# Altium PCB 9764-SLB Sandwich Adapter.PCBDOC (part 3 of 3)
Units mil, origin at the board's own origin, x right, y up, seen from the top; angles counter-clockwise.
Board outline 5593.84 x 1511.98 mil, 8 copper layers (Top Layer, MidLayer1, MidLayer2, MidLayer3, MidLayer4, MIdLayer5, MidLayer6, Bottom Layer); 137 components, 228 nets, 1508 pads, 0 vias.
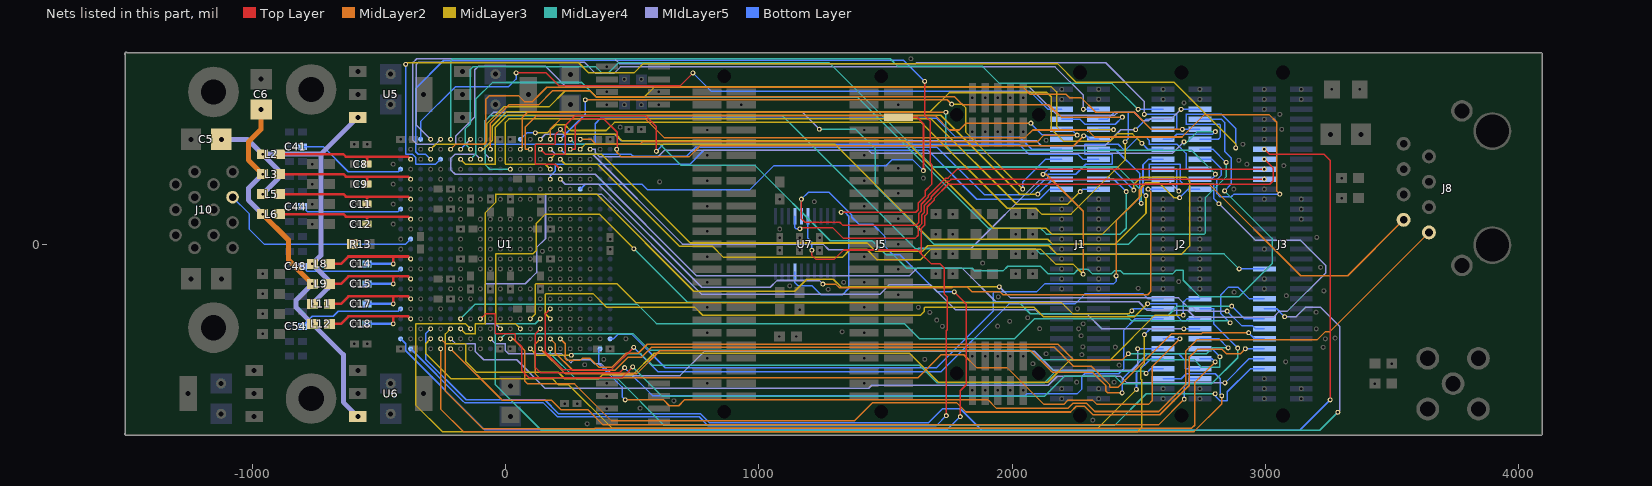
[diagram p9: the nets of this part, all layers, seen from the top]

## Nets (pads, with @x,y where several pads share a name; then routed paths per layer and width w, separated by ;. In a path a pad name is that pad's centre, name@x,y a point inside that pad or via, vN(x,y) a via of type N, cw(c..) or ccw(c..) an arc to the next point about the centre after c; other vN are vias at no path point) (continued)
SYNC3_0: J1.43 pad.0@2268.65,207 U1.T4 | length 2860.4
  MidLayer3 w6: U1.T4@177.17,295.28 157.44,315 1.15,315 0.15,316 0.15,480 13.99,493.84 1681,493.84 2017.84,157 2218.65,157 pad.0@2268.65,207
  Bottom Layer w6: pad.0@2268.65,207 2278.19,216.54 J1.43@2340.98,216.54
SYNC3_1: J1.44 U1.T5 | length 2184.1
  Bottom Layer w6: U1.T5@177.17,255.91 177.17,268.63 196.15,287.61 196.15,313 198.15,315 728.15,315 783.15,370 1667.31,370 1860.31,177 2108.2,177 2147.73,216.54 J1.44@2195.32,216.54
SYNC3_2: J1.45 pad.0@2450.15,207 U1.H3 | length 3371.7
  MidLayer4 w6: U1.H3@-137.8,334.65 -117.85,354.59 -117.85,571 -51.35,637.5 301.34,637.5 359.84,579 1389.15,579 1905.15,63 2111.15,63 2135.15,39 2426.65,39 2450.15,62.5 pad.0@2450.15,207
  Bottom Layer w6: J1.45@2340.98,255.91 2401.24,255.91 pad.0@2450.15,207
SYNC3_3: J1.46 pad.0@2101.15,197 U1.G3 | length 2700.4
  MidLayer3 w6: U1.G3@-177.17,334.65 -156.52,314 -40.85,314 -39.85,315 -39.85,460.03 8.12,508 1718.15,508 2030.15,196 2100.15,196 pad.0@2101.15,197
  Bottom Layer w6: pad.0@2101.15,197 2160.06,255.91 J1.46@2195.32,255.91
SYNC3_4: J1.47 pad.0@2480.15,213 U1.T3 | length 3417.6
  MidLayer3 w6: U1.T3@177.17,334.65 197.52,355 378.15,355 729.15,4 1428.15,4 1461.15,-29 1644.69,-29 1666.69,-7 2144.15,-7 2177.15,-40 2668.15,-40 2700.15,-8 2700.15,250 2686.15,264 2509.15,264 2480.15,235 pad.0@2480.15,213
  Bottom Layer w6: J1.47@2340.98,295.28 2397.87,295.28 pad.0@2480.15,213
SYNC3_5: J1.48 pad.0@2121.65,275 pad.0@2280.15,-119 U1.U3 | length 2861.9
  MidLayer2 w6: pad.0@2121.65,275 2134.15,275 2280.15,129 pad.0@2280.15,-119
  MidLayer3 w6: U1.U3@216.54,334.65 236.18,315 363.15,315 686.15,-8 816.15,-8 861.15,-53 1329.15,-53 1361.15,-21 1425.65,-21 1466.65,-62 1638.15,-62 1680.15,-20 2112.15,-20 2171.15,-79 2240.15,-79 pad.0@2280.15,-119
  Bottom Layer w6: pad.0@2121.65,275 2141.93,295.28 J1.48@2195.32,295.28
SYNC3_6: J1.49 pad.0@596.15,366 U1.R2 | length 2490.5
  Top Layer w6: U1.R2@137.8,374.02 157.81,354 234.15,354 236.15,356 236.15,467.5 274.65,506 552.65,506 596.15,462.5 pad.0@596.15,366
  Bottom Layer w6: pad.0@596.15,366 624.15,394 2027.15,394 2066.82,354.33 2259.51,354.33 2279.2,334.65 J1.49@2340.98,334.65
SYNC3_7: J1.50 pad.0@315.15,569 pad.0@1761.15,552 pad.0@2041.5,217 U1.U1 | length 2343.7
  MidLayer2 w6: pad.0@315.15,569 1744.15,569 pad.0@1761.15,552
  MidLayer3 w6: pad.0@1761.15,552 1802.65,552 1816.15,538.5 1816.15,442.35 pad.0@2041.5,217
  Bottom Layer w6: U1.U1@216.54,413.39 315.15,512 pad.0@315.15,569 ; pad.0@2041.5,217 2041.5,244.75 2131.4,334.65 J1.50@2195.32,334.65
SYNC3_8: J1.51 pad.0@2509.15,160.32 U1.H2 | length 3593.1
  MidLayer4 w6: U1.H2@-137.8,374.02 -157.85,394.07 -157.85,456 -138.85,475 -138.85,688.5 -126.85,700.5 355.65,700.5 381.15,675 406.15,675 447.15,716 1277.15,716 1689.15,304 2416.15,304 2509.15,211 pad.0@2509.15,160.32
  Bottom Layer w6: J1.51@2340.98,374.02 2407.04,374.02 2504.15,276.91 2504.15,165.32 pad.0@2509.15,160.32
SYNC4_0: J1.52 U1.G2 | length 2520.4
  Bottom Layer w6: U1.G2@-177.17,374.02 -158.18,393 352.15,393 354.15,395 354.15,475 375.15,496 1702.15,496 1776.15,422 2029.15,422 2077.13,374.02 J1.52@2195.32,374.02
SYNC4_1: J1.53 pad.0@439.15,374 pad.0@2282.15,427 U1.V2 | length 2339
  Top Layer w6: U1.V2@255.91,374.02 274.15,374.02 276.15,376.02 276.15,468 301.99,493.84 388.31,493.84 441.15,441 441.15,376 pad.0@439.15,374
  MidLayer2 w6: pad.0@439.15,374 439.15,362 456.15,345 726.15,345 769.15,388 2243.15,388 pad.0@2282.15,427
  Bottom Layer w6: pad.0@2282.15,427 2292.54,427 2306.15,413.39 J1.53@2340.98,413.39
SYNC4_2: J1.54 pad.0@2074.15,477 U1.P2 | length 2303.1
  MidLayer2 w6: U1.P2@98.43,374.02 80.15,374.02 79.15,375.02 79.15,462.5 122.49,505.84 1697.31,505.84 1753.15,450 1791.15,450 1818.15,477 pad.0@2074.15,477
  Bottom Layer w6: pad.0@2074.15,477 2074.15,475 2117.15,432 2174.54,432 2193.15,413.39 J1.54@2195.32,413.39
SYNC4_3: J1.55 pad.0@2399.89,451.5 U1.D2 | length 3066.7
  MidLayer3 w6: U1.D2@-295.28,374.02 -275.29,394 -85.85,394 -74.35,405.5 -74.35,473.5 -6.85,541 172.15,541 235.99,604.84 333.99,604.84 358.84,580 548.15,580 588.15,620 2155.15,620 2175.15,600 2175.15,463.5 2187.15,451.5 pad.0@2399.89,451.5
  Bottom Layer w6: J1.55@2340.98,452.76 2398.64,452.76 pad.0@2399.89,451.5
SYNC4_4: J1.56 pad.0@2256.15,430 U1.W1 | length 2054.9
  MidLayer2 w6: U1.W1@295.28,413.39 338.15,413.39 358.54,393 530.15,393 541.15,404 2100.15,404 2126.15,430 pad.0@2256.15,430
  Bottom Layer w6: J1.56@2195.32,452.76 2233.39,452.76 pad.0@2256.15,430
SYNC4_5: J1.57 pad.0@118.15,439 pad.0@2445.65,403.5 U1.N1 | length 2992.1
  MidLayer3 w6: pad.0@118.15,439 166.46,439 198.46,471 233.99,471 256.96,448.03 398.18,448.03 430.15,480 1641.15,480 1980.15,141 2093.15,141 2116.15,118 2232.15,118 2445.65,331.5 pad.0@2445.65,403.5
  Bottom Layer w6: U1.N1@59.06,413.39 84.67,439 pad.0@118.15,439 ; J1.57@2340.98,492.13 2376.15,492.13 2404.02,520 2454.99,520 2458.15,516.84 2458.15,416 pad.0@2445.65,403.5
SYNC4_6: J1.58 pad.0@2435.15,501 U1.K2 | length 2952
  MidLayer2 w6: U1.K2@-59.06,374.02 -59.06,476.79 13.15,549 130.15,549 185.15,604 334.84,604 357.84,581 1772.65,581 1803.65,550 2144.65,550 2193.65,501 pad.0@2435.15,501
  Bottom Layer w6: J1.58@2195.32,492.13 2268.15,492.13 2287.65,472.62 2406.77,472.62 pad.0@2435.15,501
SYNC4_7: J1.59 pad.0@2281.15,531.5 U1.D1 | length 3146.2
  MIdLayer5 w6: U1.D1@-295.28,413.39 -351.85,469.96 -351.85,708 -341.85,718 311.15,718 356.01,673.14 428.29,673.14 454.15,699 2169.15,699 2281.15,587 pad.0@2281.15,531.5
  Bottom Layer w6: pad.0@2281.15,531.5 J1.59@2340.98,531.5
SYNC4_8: J1.60 pad.0@42.15,675 pad.0@740.15,675 U1.C1 | length 2795
  Top Layer w6: pad.0@42.15,675 161.15,675 212.15,624 689.15,624 pad.0@740.15,675
  Bottom Layer w6: U1.C1@-334.65,413.39 -334.65,483.2 -197.85,620 11.15,620 42.15,651 pad.0@42.15,675 ; pad.0@740.15,675 813.15,602 2070.65,602 2141.15,531.5 J1.60@2195.32,531.5
SYNC5_0: J2.59 pad.0@2666.49,531.5 U1.H1 | length 3378.1
  MIdLayer5 w6: U1.H1@-137.8,413.39 -158.18,393 -194.85,393 -196.85,395 -196.85,425 -120.85,501 -120.85,687.5 -107.35,701 159.15,701 240.15,620 2067.15,620 2179.81,507.34 2403.81,507.34 2416.46,520 2481.66,520 2515.66,486 2537.3,486 2545.4,494.1 2629.1,494.1 pad.0@2666.49,531.5
  Bottom Layer w6: pad.0@2666.49,531.5 J2.59@2740.98,531.5
SYNC5_1: J2.60 pad.0@2496.91,531.5 U1.F1 | length 3206.8
  MidLayer4 w6: U1.F1@-216.54,413.39 -216.54,722 -207.54,731 1519.15,731 1549.15,701 1883.15,701 1950.15,634 2394.4,634 pad.0@2496.91,531.5
  Bottom Layer w6: pad.0@2496.91,531.5 J2.60@2595.32,531.5
SYNC5_2: J2.57 pad.0@2838.15,209.5 U1.V1 | length 3915.7
  MidLayer4 w6: U1.V1@255.91,413.39 276.29,393 611.15,393 694.15,310 985.15,310 1282.15,13 1447.31,13 1503.31,-43 1531.15,-43 1584.15,-96 1842.62,-96 1852.62,-106 1964.2,-106 1982.2,-88 2112.29,-88 2142.29,-118 2243.18,-118 2261.18,-100 2298.84,-100 2316.84,-118 2391.3,-118 2403.3,-106 2428.55,-106 2440.55,-118 2632.37,-118 2647.41,-102.96 2674.23,-102.96 2675.28,-104 2675.28,-142.63 2741.65,-209 2894.34,-209 3025.65,-77.69 3025.65,22 pad.0@2838.15,209.5
  Bottom Layer w6: J2.57@2740.98,492.13 2825.65,492.13 2838.15,479.63 2838.15,366.51 2864.15,340.51 2864.15,235.5 pad.0@2838.15,209.5
SYNC5_3: J2.58 pad.0@2487.15,451 U1.R1 | length 2527.4
  MIdLayer5 w6: U1.R1@137.8,413.39 157.41,433 430.15,433 456.15,407 2096.15,407 2115.15,388 2365.9,388 2428.9,451 pad.0@2487.15,451
  Bottom Layer w6: pad.0@2487.15,451 2528.28,492.13 J2.58@2595.32,492.13
SYNC5_4: J2.55 pad.0@2672.15,452.5 U1.F2 | length 3249.9
  MidLayer2 w6: U1.F2@-216.54,374.02 -197.55,393 -80.85,393 -77.85,396 -77.85,570 -61.85,586 51.15,586 75.28,561.87 106.1,561.87 163.08,618.84 2042.31,618.84 2070.15,591 2212.15,591 2225.15,578 2272.15,578 2330.15,520 2481.66,520 2549.16,452.5 pad.0@2672.15,452.5
  Bottom Layer w6: pad.0@2672.15,452.5 2672.41,452.76 J2.55@2740.98,452.76
SYNC5_5: J2.56 pad.0@2521.65,511.63 U1.E1 | length 3687.9
  MIdLayer5 w6: U1.E1@-255.91,413.39 -276.29,393 -348.35,393 -364.85,409.5 -364.85,716.5 -350.35,731 431.15,731 450.15,712 1619.15,712 1622.15,715 2369.15,715 2521.65,562.5 pad.0@2521.65,511.63
  Bottom Layer w6: pad.0@2521.65,511.63 2649.15,511.63 2650.15,510.63 2650.15,453.76 2649.15,452.76 J2.56@2595.32,452.76
SYNC5_6: J2.53 pad.0@2882.15,379 pad.0@-393.85,709 U1.E3 | length 4591.7
  MidLayer3 w6: pad.0@-393.85,709 -387.85,715 289.15,715 329.15,675 507.15,675 544.15,712 2178.65,712 2252.65,638 2639.38,638 2882.15,395.23 pad.0@2882.15,379
  Bottom Layer w6: pad.0@-393.85,709 -393.85,356 -392.85,355 -367.72,355 -353.85,341.13 -353.85,316 -352.85,315 -275.55,315 U1.E3@-255.91,334.65 ; J2.53@2740.98,413.39 2813.49,413.39 2822.15,422.04 2822.15,468.69 2818.21,472.62 2687.15,472.62 2686.15,473.62 2686.15,510.99 2687.15,511.99 2825.66,511.99 2882.15,455.5 pad.0@2882.15,379
SYNC5_7: J2.54 pad.0@2678.15,403.5 pad.0@2802.15,444 U1.Y2 | length 2774.2
  MIdLayer5 w6: U1.Y2@334.65,374.02 354.15,374.02 355.15,373.02 355.15,360.47 370.62,345 603.15,345 628.15,370 1433.15,370 1444.15,359 2633.65,359 pad.0@2678.15,403.5
  MidLayer4 w6: pad.0@2678.15,403.5 2678.15,391 2684.4,397.25 2731.15,444 pad.0@2802.15,444
  Bottom Layer w6: J2.54@2595.32,413.39 2630.15,413.39 2649.76,433 2791.15,433 pad.0@2802.15,444
SYNC5_8: J2.51 pad.0@1239.15,453 pad.0@2844.15,322 U1.K3 | length 3771.6
  MIdLayer5 w6: U1.K3@-59.06,334.65 -78.85,354.44 -78.85,488 -46.85,520 1172.15,520 pad.0@1239.15,453
  MidLayer4 w6: pad.0@1239.15,453 1382.15,453 1460.15,375 1460.15,230 1690.15,0 2460.15,0 2499.15,39 2758.15,39 2761.15,42 2761.15,182 2844.15,265 pad.0@2844.15,322
  Bottom Layer w6: J2.51@2740.98,374.02 2792.13,374.02 pad.0@2844.15,322
SYNC6_0: J2.52 pad.0@2512.07,397.42 U1.J2 | length 3010
  MidLayer3 w6: U1.J2@-98.43,374.02 -86.85,374.02 -51.85,409.02 -51.85,465 5.65,522.5 1676.65,522.5 1752.15,598 2137.15,598 2154.15,581 2154.15,454 2202.15,406 2385.72,406 2414.07,434.34 2475.15,434.34 pad.0@2512.07,397.42
  Bottom Layer w6: pad.0@2512.07,397.42 2535.48,374.02 J2.52@2595.32,374.02
SYNC6_1: J2.49 pad.0@3056.15,197 U1.T1 | length 3779.6
  MidLayer2 w6: U1.T1@177.17,413.39 177.17,453.76 217.25,493.84 552.31,493.84 626.15,420 2051.01,420 2081.01,450 2297.4,450 2325.05,422.34 2670.49,422.34 2759.15,511 3014.15,511 3044.15,481 3044.15,209 pad.0@3056.15,197
  Bottom Layer w6: J2.49@2740.98,334.65 2788.15,334.65 2825.65,297.15 2825.65,272.15 2808.15,254.65 2808.15,199.11 2820.77,186.5 2864.65,186.5 2875.15,197 pad.0@3056.15,197
SYNC6_2: J2.50 pad.0@2528.15,191 U1.W2 | length 2738.4
  MidLayer3 w6: U1.W2@295.28,374.02 314.26,393 1302.15,393 1676.15,19 2140.15,19 2159.15,0 2407.15,0 2528.15,121 pad.0@2528.15,191
  Bottom Layer w6: pad.0@2528.15,191 2516.35,202.8 2516.35,312.85 2538.15,334.65 J2.50@2595.32,334.65
SYNC6_3: J2.47 U1.U2 | length 3109.1
  Bottom Layer w6: U1.U2@216.54,374.02 236.55,354 496.15,354 504.15,346 715.15,346 751.15,382 1703.15,382 1890.15,195 2068.15,195 2131.15,258 2140.04,258 2141.04,259 2141.04,274.48 2142.15,275.59 2250.65,275.59 2290.06,315 2394.26,315 2395.26,316 2395.26,353.04 2394.15,354.15 2287.15,354.15 2286.15,355.15 2286.15,392.52 2287.15,393.52 2419.04,393.52 2439.56,373 2449.65,373 2500.65,424 2525.65,424 2540.15,409.5 2540.15,394.52 2541.15,393.52 2650.15,393.52 2686.15,357.52 2686.15,296.28 2687.15,295.28 J2.47@2740.98,295.28
SYNC6_4: J2.48 pad.0@2657.74,209 U1.T2 | length 2921.2
  MIdLayer5 w6: U1.T2@177.17,374.02 197.18,354 344.65,354 698.65,0 1253.15,0 1276.15,-23 1625.15,-23 1631.15,-17 1838.15,-17 2108.15,253 2613.74,253 pad.0@2657.74,209
  Bottom Layer w6: J2.48@2595.32,295.28 2649.15,295.28 2650.15,294.28 2650.15,216.59 pad.0@2657.74,209
SYNC6_5: J2.45 pad.0@1738.65,520 pad.0@2802.15,276 U1.N2 | length 3123.7
  MidLayer2 w6: U1.N2@59.06,374.02 67.15,382.11 67.15,500 87.15,520 pad.0@1738.65,520
  MidLayer4 w6: pad.0@1738.65,520 1738.65,387.5 1756.15,370 2708.15,370 pad.0@2802.15,276
  Bottom Layer w6: J2.45@2740.98,255.91 2787.06,255.91 2802.15,271 pad.0@2802.15,276
SYNC6_6: J2.46 pad.0@2816.15,159 U1.J3 | length 5044.3
  MIdLayer5 w6: U1.J3@-98.43,334.65 -117.78,354 -199.35,354 -215.85,337.5 -215.85,292.5 -198.35,275 354.15,275 754.15,-125 1595.15,-125 1625.15,-95 1802.15,-95 1935.27,-228.12 2499.15,-228.12 2532.03,-261 2693.34,-261 2720.99,-288.66 3031.76,-288.66 3055.51,-264.91 3086.58,-264.91 3238.15,-113.34 3238.15,-85.5 3137.65,15 2960.15,15 pad.0@2816.15,159
  Bottom Layer w6: J2.46@2595.32,255.91 2541.15,255.91 2540.15,256.91 2540.15,314 2541.15,315 2661.15,315 2663.15,313 2663.15,248.72 2675.65,236.22 2794.15,236.22 2795.26,235.11 2795.26,179.89 pad.0@2816.15,159
SYNC6_7: J2.43 pad.0@217.15,452 pad.0@2660.61,183 U1.U4 | length 3164.9
  Top Layer w6: U1.U4@216.54,295.28 196.81,315 119.15,315 118.15,316 118.15,392 120.15,394 195.15,394 196.15,395 196.15,431 pad.0@217.15,452
  MidLayer3 w6: pad.0@217.15,452 236.15,433 435.38,433 461.38,407 1580.15,407 1925.15,62 2133.15,62 2156.15,39 2356.15,39 2509.15,192 2509.15,225.5 2525.65,242 2579.15,242 2638.15,183 pad.0@2660.61,183
  Bottom Layer w6: pad.0@2660.61,183 2694.15,216.54 J2.43@2740.98,216.54
SYNC6_8: J2.44 pad.0@1253.15,-158 pad.0@2536.15,216.54 U1.U5 | length 3017.2
  MidLayer2 w6: pad.0@1253.15,-158 1303.15,-158 1317.15,-172 1763.15,-172 1766.15,-169 1822.15,-169 1842.15,-189 1953.24,-189 1964.24,-200 2534.65,-200 2547.15,-187.5 2547.15,205.54 pad.0@2536.15,216.54
  MIdLayer5 w6: U1.U5@216.54,255.91 236.44,236 367.65,236 774.65,-171 1045.15,-171 1072.15,-144 1239.15,-144 pad.0@1253.15,-158
  Bottom Layer w6: pad.0@2536.15,216.54 J2.44@2595.32,216.54
SYNC7_0: J2.21 pad.0@2675.15,-280.5 U1.F20 | length 3395.8
  MidLayer3 w6: U1.F20@-216.54,-334.65 -236.85,-354.96 -236.85,-391 -234.85,-393 -159.85,-393 -156.85,-396 -156.85,-463.5 -114.35,-506 208.81,-506 234.15,-531.34 367.49,-531.34 383.84,-515 503.15,-515 587.15,-431 1594.31,-431 1709.31,-546 2140.15,-546 2230.15,-456 2388.72,-456 2564.22,-280.5 pad.0@2675.15,-280.5
  Bottom Layer w6: pad.0@2675.15,-280.5 2675.15,-229.53 2688.15,-216.53 J2.21@2740.98,-216.53
SYNC7_1: J2.22 pad.0@506.15,-408 U1.T18 | length 2856.8
  Top Layer w6: U1.T18@177.17,-255.91 157.15,-275.92 157.15,-426.5 225.99,-495.34 418.81,-495.34 pad.0@506.15,-408
  Bottom Layer w6: pad.0@506.15,-408 602.15,-504 1719.34,-504 1986.93,-236.4 2247.75,-236.4 2287.15,-197 2517.38,-197 2536.91,-216.53 J2.22@2595.32,-216.53
SYNC7_2: J2.19 pad.0@502.15,-485 pad.0@2889.99,-410.48 U1.J19 | length 3650.8
  Top Layer w6: U1.J19@-98.43,-295.28 -79.15,-276 -40.85,-276 -39.85,-277 -39.85,-352 -36.85,-355 38.15,-355 39.15,-356 39.15,-380.76 64.15,-405.76 64.15,-498.76 92.39,-527 460.15,-527 pad.0@502.15,-485
  MidLayer4 w6: pad.0@502.15,-485 617.15,-600 2128.15,-600 2205.37,-522.78 2406.12,-522.78 2434.34,-551 2788.05,-551 2889.99,-449.06 pad.0@2889.99,-410.48
  Bottom Layer w6: J2.19@2740.98,-255.91 2795.15,-255.91 2795.31,-256.06 2795.31,-315.79 pad.0@2889.99,-410.48
SYNC7_3: J2.20 pad.0@2472.15,-264 U1.P19 | length 2679
  MidLayer3 w6: U1.P19@98.43,-295.28 118.15,-275.55 118.15,-159 120.15,-157 440.15,-157 514.15,-231 2194.4,-231 2238.15,-274.75 2461.4,-274.75 pad.0@2472.15,-264
  Bottom Layer w6: pad.0@2472.15,-264 2480.24,-255.91 J2.20@2595.32,-255.91
SYNC7_4: J2.17 pad.0@2534.15,-236.04 U1.T19 | length 2840.2
  MidLayer3 w6: U1.T19@177.17,-295.28 157.15,-275.26 157.15,-199 159.15,-197 347.15,-197 400.15,-250 748.15,-250 779.15,-281 1638.15,-281 1652.15,-267 1652.15,-252 1654.15,-250 2086.8,-250 2123.8,-287 2483.19,-287 pad.0@2534.15,-236.04
  Bottom Layer w6: pad.0@2534.15,-236.04 2649.15,-236.04 2650.15,-237.04 2650.15,-283.05 2670.4,-303.3 2684.92,-303.3 2692.94,-295.28 J2.17@2740.98,-295.28
SYNC7_5: J2.18 pad.0@470.15,-488 U1.R20 | length 2944.6
  Top Layer w6: U1.R20@137.8,-334.65 118.15,-354.29 118.15,-487.5 138.65,-508 450.15,-508 pad.0@470.15,-488
  Bottom Layer w6: pad.0@470.15,-488 580.15,-598 2051.52,-598 2059.15,-590.37 2257.78,-590.37 2274.15,-574 2274.15,-524 2286.52,-511.63 2420.52,-511.63 2441.15,-491 2441.15,-451.19 2439.73,-449.76 2439.73,-341.72 2486.17,-295.28 J2.18@2595.32,-295.28
SYNC7_6: J2.15 pad.0@2677.33,-334.65 U1.L20 | length 3601.7
  MIdLayer5 w6: U1.L20@-19.69,-334.65 -39.33,-315 -77.85,-315 -78.85,-314 -78.85,-158 -77.85,-157 78.65,-157 123.15,-112.5 123.15,-14 158.15,21 158.15,196 159.15,197 379.15,197 774.15,-198 1478.15,-198 1515.15,-161 1678.15,-161 1776.15,-259 2092.11,-259 2109.11,-276 2295.15,-276 2353.8,-334.65 pad.0@2677.33,-334.65
  Bottom Layer w6: pad.0@2677.33,-334.65 J2.15@2740.98,-334.65
SYNC7_7: J2.16 pad.0@2522.15,-357.5 U1.H20 | length 3917.1
  MidLayer3 w6: U1.H20@-137.8,-334.65 -157.44,-315 -352.85,-315 -354.85,-317 -354.85,-635 -248.85,-741 2494.15,-741 2511.15,-724 2511.15,-536 2508.15,-533 2508.15,-486 2522.15,-472 pad.0@2522.15,-357.5
  Bottom Layer w6: pad.0@2522.15,-357.5 2545,-334.65 J2.16@2595.32,-334.65
SYNC7_8: J2.13 pad.0@2458.57,-433 pad.0@2852.15,-410 U1.U21 | length 2930.4
  MidLayer2 w6: U1.U21@216.54,-374.02 236.15,-393.63 236.15,-451.91 242.24,-458 295.99,-458 303.99,-450 332.96,-450 369.31,-486.34 420.15,-486.34 475.49,-431 524.15,-431 559.31,-395.84 2180.73,-395.84 2240.88,-456 2435.57,-456 pad.0@2458.57,-433
  MidLayer4 w6: pad.0@2458.57,-433 2767.31,-433 2790.31,-410 pad.0@2852.15,-410
  Bottom Layer w6: J2.13@2740.98,-374.02 2816.17,-374.02 pad.0@2852.15,-410
SYNC8_0: J2.14 pad.0@2662.15,-374.02 U1.R21 | length 3082.2
  MidLayer2 w6: U1.R21@137.8,-374.02 118.15,-393.66 118.15,-512.5 132.65,-527 1629.15,-527 1718.99,-437.16 1809.31,-437.16 1860.98,-488.83 1981.48,-488.83 2125.65,-633 2203.7,-633 2220.7,-616 2317.48,-616 2334.48,-633 2538.15,-633 2552.15,-619 2552.15,-484.02 pad.0@2662.15,-374.02
  Bottom Layer w6: J2.14@2595.32,-374.02 pad.0@2662.15,-374.02
SYNC8_1: J2.11 pad.0@2820.15,-445 U1.L21 | length 3034.1
  MidLayer4 w6: U1.L21@-19.69,-374.02 -0.67,-355 505.15,-355 570.15,-420 2068.15,-420 2104.15,-456 2717.15,-456 2747.15,-486 2818.15,-486 2820.15,-484 pad.0@2820.15,-445
  Bottom Layer w6: J2.11@2740.98,-413.39 2788.54,-413.39 pad.0@2820.15,-445
SYNC8_2: J2.12 pad.0@2495.15,-413.39 U1.K21 | length 2882.7
  MIdLayer5 w6: U1.K21@-59.06,-374.02 -39.07,-394 -0.85,-394 0.15,-395 0.15,-421 11.38,-432.23 221.15,-432.23 256.92,-468 258.92,-468 269.92,-457 336.15,-457 352.15,-473 379.12,-473 425.12,-519 689.15,-519 785.15,-423 2087.15,-423 2162.12,-497.97 2475.65,-497.97 2495.15,-478.47 pad.0@2495.15,-413.39
  Bottom Layer w6: pad.0@2495.15,-413.39 J2.12@2595.32,-413.39
SYNC8_3: J2.9 pad.0@2801.15,-465.26 U1.E21 | length 3587.6
  MidLayer2 w6: U1.E21@-255.91,-374.02 -236.85,-393.07 -236.85,-581 -88.85,-729 352.15,-729 354.15,-727 2708.15,-727 2720.15,-715 2720.15,-546.26 pad.0@2801.15,-465.26
  Bottom Layer w6: J2.9@2740.98,-452.76 2788.65,-452.76 pad.0@2801.15,-465.26
SYNC8_4: J2.10 pad.0@2490.65,-574.06 U1.D21 | length 3250.7
  MidLayer3 w6: U1.D21@-295.28,-374.02 -314.85,-393.59 -314.85,-432 -215.85,-531 184.46,-531 209.46,-556 250.15,-556 422.15,-728 2336.71,-728 pad.0@2490.65,-574.06
  Bottom Layer w6: pad.0@2490.65,-574.06 2490.65,-509.5 2547.39,-452.76 J2.10@2595.32,-452.76
SYNC8_5: J2.7 pad.0@2433.65,-587.47 U1.R22 | length 2901.5
  MidLayer2 w6: U1.R22@137.8,-413.39 235.41,-511 519.25,-511 609.25,-421 2073.95,-421 2159.89,-506.94 2318.09,-506.94 2368.75,-557.6 2368.75,-578.9 2377.31,-587.47 pad.0@2433.65,-587.47
  Bottom Layer w6: pad.0@2433.65,-587.47 2433.65,-533.5 2534.15,-433 2657.15,-433 2682.53,-458.38 2682.53,-491 2683.65,-492.13 J2.7@2740.98,-492.13
SYNC8_6: J2.8 pad.0@260.15,-439 pad.0@2528.28,-511 U1.P22 | length 2586.8
  MidLayer3 w6: U1.P22@98.43,-413.39 124.04,-439 pad.0@260.15,-439
  MidLayer4 w6: pad.0@260.15,-439 265.15,-434 535.15,-434 579.15,-478 1633.15,-478 1702.15,-547 2128.15,-547 2173.49,-501.66 2518.93,-501.66 pad.0@2528.28,-511
  Bottom Layer w6: pad.0@2528.28,-511 2547.15,-492.13 J2.8@2595.32,-492.13
SYNC8_7: J2.5 pad.0@2679.15,-612 U1.F22 | length 3194.8
  MidLayer2 w6: U1.F22@-216.54,-413.39 -12.92,-617 182.15,-617 219.15,-654 326.15,-654 386.15,-714 2577.15,-714 pad.0@2679.15,-612
  Bottom Layer w6: pad.0@2679.15,-612 2679.15,-562.84 2696.25,-545.74 2696.25,-531.5 J2.5@2740.98,-531.5
SYNC8_8: J2.6 pad.0@2827.15,-599 U1.E22 | length 3747.2
  MidLayer2 w6: U1.E22@-255.91,-413.39 -255.91,-650.94 -165.85,-741 359.15,-741 360.15,-740 2718.15,-740 2827.15,-631 pad.0@2827.15,-599
  Bottom Layer w6: J2.6@2595.32,-531.5 2667.15,-531.5 2686.66,-511.99 2801.15,-511.99 2820.95,-531.79 2820.95,-592.8 pad.0@2827.15,-599
TCK: J3.50 pad.0@1209.65,-24.61 pad.0@1740.16,-677.17 pad.0@2995.32,334.65 U1.B22 U7.6 | length 5286.7
  Top Layer w6: pad.0@1209.65,-24.61 1209.65,-45.28 1225.39,-61.02 1297.24,-61.02 1334.65,-23.62 1625.98,-23.62 1641.28,-38.91 ; pad.0@1740.16,-677.17 1740.16,-342.52 1744.09,-338.58 1744.09,-208.66 1732.28,-196.85 1732.28,-94.49 1716.54,-78.74 1681.1,-78.74 1641.28,-38.91 ; pad.0@2995.32,334.65 3030,299.96 3030,250 3016.22,236.22 1748.03,236.22 1693,181.19 1693,175.12 1664.94,147.05 1664.94,119.93 1655.89,110.88 1655.89,75.69 1641.28,61.07 1641.28,-38.91
  Bottom Layer w6: U1.B22@-374.02,-413.39 -166.34,-621.06 -165.91,-621.06 -159.97,-627 150.03,-627 205.03,-682 765.03,-682 800.03,-717 1674.97,-717 1675.44,-716.54 1700.79,-716.54 pad.0@1740.16,-677.17 ; U7.6@1193.9,109.25 1193.9,22.64 1209.65,6.89 pad.0@1209.65,-24.61
TDI: J3.46 pad.0@1162.4,60.04 pad.0@2995.32,255.91 U7.4 | length 2072.7
  Top Layer w6: pad.0@1162.4,60.04 1167.32,64.96 1291.34,64.96 1332.68,23.62 1618.11,23.62 1629.28,34.79 1629.28,66.05 1643.89,80.66 1643.89,115.85 1652.94,124.9 1652.94,152.03 1681,180.09 1681,186.16 1743.06,248.22 1752.16,248.22 1759.85,255.91 pad.0@2995.32,255.91
  Bottom Layer w6: U7.4@1142.72,109.25 1142.72,64.96 1147.64,60.04 pad.0@1162.4,60.04
TDI_F: pad.0@1325,125 pad.0@1654.53,641.73 U1.D3 U7.17 | length 3866.6
  Top Layer w6: pad.0@1325,125 1619.09,125 1628.94,134.84 1628.94,163 1629.97,163 1657,190.03 1657,210.03 1682,235.03 1682,314.97 1677,319.97 1677,484.97 1654.53,507.44 pad.0@1654.53,641.73
  Bottom Layer w6: U1.D3@-295.28,334.65 -314.96,354.33 -344.49,354.33 -354.33,364.17 -354.33,614.17 -243.11,725.39 1570.87,725.39 pad.0@1654.53,641.73 ; U7.17@1142.72,-109.25 1142.72,-152.72 1155,-165 1210,-165 1245,-200 1330,-200 1355,-175 1355,110 1340,125 pad.0@1325,125
TDO: J3.52 pad.0@2995.32,374.02 pad.0@3255,-615 U1.D20 | length 5132.7
  Top Layer w6: pad.0@2995.32,374.02 3014.33,355 3230,355 3255,330 pad.0@3255,-615
  Bottom Layer w6: U1.D20@-295.28,-334.65 -315,-354.37 -315,-455 -155,-615 155,-615 210,-670 770,-670 805,-705 1670,-705 1725,-650 1795,-650 1880,-735 3135,-735 pad.0@3255,-615
TMS: J3.48 pad.0@1168.31,177.17 pad.0@1771.65,-188.98 pad.0@1795.28,-681.1 pad.0@2995.32,295.28 U1.A21 U7.5 | length 5836.6
  Top Layer w6: pad.0@1168.31,177.17 1168.31,99.41 1182.09,85.63 1319.88,85.63 1330.71,74.8 1621.06,74.8 1631.89,85.63 1631.89,120.82 1640.94,129.87 1640.94,157 1669,185.06 1669,191.13 1738.09,260.22 1747.19,260.22 1782.25,295.28 pad.0@2995.32,295.28 ; pad.0@1771.65,-188.98 1818.9,-236.22 1818.9,-555.12 1795.28,-578.74 pad.0@1795.28,-681.1
  Bottom Layer w6: U1.A21@-413.39,-374.02 -393.7,-393.7 -393.7,-421.26 -82.68,-732.28 1744.09,-732.28 pad.0@1795.28,-681.1 ; U7.5@1168.31,109.25 pad.0@1168.31,177.17 1195.87,204.72 1277.25,204.72 1367,114.97 1367,106.03 1395.03,78 1450.03,78 1498,30.03 1498,-9.97 1530.03,-42 1557.75,-42 1704.72,-188.98 pad.0@1771.65,-188.98
TP+: J8.1 pad.0@2410.15,-126 U1.AB21 | length 3935.5
  MidLayer2 w6: pad.0@2410.15,-126 2410.15,91 2501.15,182 2501.15,212.5 2525.65,237 2777.15,237 3139.15,-125 3324.41,-125 J8.1@3544.97,95.56
  Bottom Layer w6: U1.AB21@413.39,-374.02 426.29,-374.02 445.15,-355.16 498.11,-355.16 630.95,-488 1701.15,-488 1926.15,-263 1926.15,-191.41 1928.56,-189 2096.15,-189 2127.67,-157.48 2400.15,-157.48 2410.15,-147.48 pad.0@2410.15,-126
TP-: J8.2 pad.0@472.65,-615 U1.AA22 | length 3844.4
  MidLayer2 w6: pad.0@472.65,-615 623.81,-615 646.81,-638 683.84,-638 706.84,-615 1904.15,-615 1938.15,-649 2219.59,-649 2239.98,-628.61 2293.15,-628.61 2325.54,-661 2578.15,-661 2685.15,-554 2685.15,-422.5 2730.49,-377.16 3204.81,-377.16 3236.4,-345.56 3253.85,-345.56 J8.2@3644.97,45.56
  Bottom Layer w6: U1.AA22@374.02,-413.39 368.15,-419.25 368.15,-472.26 460.15,-564.26 460.15,-602.5 pad.0@472.65,-615
TRSTN: J5.23 pad.0@1650,290 U1.W6 | length 1732
  Top Layer w6: J5.23@1550.65,500 1625,500 1650,475 pad.0@1650,290
  Bottom Layer w6: U1.W6@295.28,216.54 314.96,236.22 538.78,236.22 560,215 965,215 1058.07,308.07 1500.98,308.07 1524.61,331.69 1608.31,331.69 pad.0@1650,290
TTC_BCR: J3.28 pad.0@2895.57,-98.42 U1.M4 | length 3613
  MidLayer4 w6: U1.M4@19.69,295.28 -61.85,295.28 -78.85,312.28 -78.85,487.5 -60.35,506 1093.15,506 1617.15,-18 2091.15,-18 2112.15,-39 2836.15,-39 pad.0@2895.57,-98.42
  Bottom Layer w6: pad.0@2895.57,-98.42 J3.28@2995.32,-98.42
TTC_BRCST2: J3.18 pad.0@507.15,-19 pad.0@2866.33,-244.96 U1.N20 | length 3745.4
  MidLayer3 w6: U1.N20@59.06,-334.65 39.41,-315 -37.85,-315 -38.85,-314 -38.85,-40 -37.85,-39 108.15,-39 122.15,-25 122.15,82 158.15,118 370.15,118 pad.0@507.15,-19
  MidLayer4 w6: pad.0@507.15,-19 718.15,-230 2026.63,-230 2071.63,-275 2451.15,-275 2459.1,-282.95 2613.86,-282.95 2651.84,-244.96 pad.0@2866.33,-244.96
  Bottom Layer w6: pad.0@2866.33,-244.96 2916.65,-295.28 J3.18@2995.32,-295.28
TTC_BRCST3: J3.16 pad.0@1949.15,-169 pad.0@2848.15,-265 U1.G20 | length 3967.2
  MIdLayer5 w6: pad.0@1949.15,-169 1993.15,-213 2656.84,-213 2690.92,-247.08 2708.57,-247.08 2726.49,-265 pad.0@2848.15,-265
  MidLayer3 w6: U1.G20@-177.17,-334.65 -156.81,-355 -119.85,-355 -118.85,-354 -118.85,-317 -116.85,-315 -79.85,-315 -78.85,-314 -78.85,124 -38.85,164 -38.85,196 -37.85,197 360.15,197 743.15,-186 1142.15,-186 1188.99,-139.16 1294.15,-139.16 1325.99,-171 1352.57,-171 1354.57,-169 pad.0@1949.15,-169
  Bottom Layer w6: pad.0@2848.15,-265 2905.15,-322 2947.5,-322 2960.15,-334.65 J3.16@2995.32,-334.65
TTC_BRCST4: J3.14 pad.0@2933.15,-350 U1.T21 | length 3097.3
  MidLayer2 w6: U1.T21@177.17,-374.02 196.15,-393 196.15,-429 265.49,-498.34 432.32,-498.34 484.66,-446 538.15,-446 576.31,-407.84 2167.51,-407.84 2242.24,-482.57 2312.72,-482.57 2384.65,-554.5 2384.65,-563 2386.65,-565 2417.84,-565 2628.39,-354.45 2747.35,-354.45 2751.81,-350 pad.0@2933.15,-350
  Bottom Layer w6: pad.0@2933.15,-350 2957.17,-374.02 J3.14@2995.32,-374.02
TTC_BRCST5: J3.12 pad.0@2920.26,-413.39 U1.M21 | length 3434.7
  MidLayer2 w6: U1.M21@19.69,-374.02 30.17,-374.02 75.65,-419.5 75.65,-539.5 88.15,-552 273.15,-552 419.15,-698 1377.15,-698 1448.15,-627 1782.15,-627 1818.15,-663 2230.61,-663 2253.01,-640.61 2285.76,-640.61 2319.15,-674 2582.12,-674 2699.15,-556.97 2699.15,-447 2730.99,-415.16 2828.13,-415.16 2845.98,-433 2900.65,-433 pad.0@2920.26,-413.39
  Bottom Layer w6: pad.0@2920.26,-413.39 J3.12@2995.32,-413.39
TTC_BRCST6: J3.10 pad.0@2839.91,-548 U1.F21 | length 3379.3
  MIdLayer5 w6: U1.F21@-216.54,-374.02 -197.55,-393 -120.85,-393 -118.85,-395 -118.85,-424 -85.85,-457 44.65,-457 156.65,-569 1434.15,-569 1445.65,-557.5 2142.65,-557.5 2178.15,-522 2427.49,-522 2453.49,-548 pad.0@2839.91,-548
  Bottom Layer w6: pad.0@2839.91,-548 2935.15,-452.76 J3.10@2995.32,-452.76
TTC_BRCST7: J3.8 pad.0@2801.15,-591 U1.T22 | length 3094.4
  MidLayer4 w6: U1.T22@177.17,-413.39 177.17,-431.69 276.64,-531.16 442.31,-531.16 627.15,-716 2404.15,-716 2529.15,-591 pad.0@2801.15,-591
  Bottom Layer w6: pad.0@2801.15,-591 2801.15,-600 2819.15,-618 2848.15,-618 2849.15,-617 2849.15,-583.13 2940.15,-492.13 J3.8@2995.32,-492.13
TTC_BRCST_STRB1: J3.20 pad.0@3075.15,-287 pad.0@3285.15,-664 U1.R19 | length 4552.3
  MIdLayer5 w6: pad.0@3075.15,-287 3120.01,-287 3157.01,-250 3217.9,-250 3293.15,-325.25 3293.15,-656 pad.0@3285.15,-664
  MidLayer4 w6: U1.R19@137.8,-295.28 118.07,-315 -37.85,-315 -39.85,-317 -39.85,-554 141.15,-735 3214.15,-735 pad.0@3285.15,-664
  Bottom Layer w6: J3.20@2995.32,-255.91 3044.06,-255.91 pad.0@3075.15,-287
TTC_CLK_DES_1: J3.22 pad.0@2860.15,-310.81 U1.G19 | length 3487.6
  MidLayer4 w6: U1.G19@-177.17,-295.28 -118.89,-237 519.14,-237 596.14,-314 1574.15,-314 1634.15,-374 2009.32,-374 2088.32,-295 2463.42,-295 2471.72,-303.3 2852.64,-303.3 pad.0@2860.15,-310.81
  Bottom Layer w6: pad.0@2860.15,-310.81 2822.33,-272.99 2822.33,-201.82 2854.15,-170 2890.62,-170 2937.15,-216.53 J3.22@2995.32,-216.53
TX/R\X\: J10.3 pad.0@-604.33,0 R13.2 U1.B11 | length 823.3
  Bottom Layer w6: J10.3@-1076.85,185 -1011.81,119.96 -1011.81,59.06 -952.76,0 pad.0@-604.33,0 -393.7,0 U1.B11@-374.02,19.69
TX_A: C41.2 U1.A4 | length 433.2
  Bottom Layer w6: C41.2@-801.77,383.86 -718.5,383.86 -620.08,285.43 -423.23,285.43 U1.A4@-413.39,295.28
TX_B: C44.2 U1.A8 | length 400.6
  Bottom Layer w6: C44.2@-801.77,147.64 -782.09,127.95 -423.23,127.95 U1.A8@-413.39,137.8
TX_C: C48.2 U1.A14 | length 400.6
  Bottom Layer w6: C48.2@-801.77,-88.58 -782.09,-108.27 -423.23,-108.27 U1.A14@-413.39,-98.43
TX_D: C54.2 U1.A18 | length 416.9
  Bottom Layer w6: C54.2@-801.77,-324.8 -762.4,-285.43 -679.13,-285.43 -659.45,-265.75 -423.23,-265.75 U1.A18@-413.39,-255.91
VTRX: C6.1 L3.2 L6.2 L9.2 L12.2 pad.0@-582.68,-681.1 pad.0@-761.81,-157.48 pad.0@-761.81,-314.96 pad.0@-958.66,118.11 pad.0@-958.66,275.59 pad.0@-964.57,530.55 U6.3 | length 1510.1
  MidLayer2 w19.68: pad.0@-964.57,530.55 -964.57,452.76 -1013.78,403.54 -1013.78,330.71 pad.0@-958.66,275.59 ; pad.0@-958.66,118.11 -856.3,15.75 -856.3,-62.99 pad.0@-761.81,-157.48
  MIdLayer5 w19.68: pad.0@-958.66,118.11 -1013.78,173.23 -1013.78,220.47 pad.0@-958.66,275.59 ; pad.0@-761.81,-157.48 -826.77,-222.44 -826.77,-250 pad.0@-761.81,-314.96 -639.76,-437.01 -639.76,-624.01 pad.0@-582.68,-681.1
VTRX1: C9.1 L3.1 U1.B5 | length 557.6
  Top Layer w10: L3.1@-891.73,275.59 -639.76,275.59 -629.92,265.75 -551.18,265.75 ; C9.1@-545.87,236.22 -545.87,260.43 -551.18,265.75 ; U1.B5@-374.02,255.91 -383.86,265.75 -551.18,265.75
VTRX2: C12.1 L6.1 U1.B9 | length 557.6
  Top Layer w10: L6.1@-891.73,118.11 -639.76,118.11 -629.92,108.27 -551.18,108.27 ; C12.1@-545.87,78.74 -545.87,102.95 -551.18,108.27 ; U1.B9@-374.02,98.43 -383.86,108.27 -551.18,108.27
VTRX3: C15.1 L9.1 pad.0@-442.91,-157.48 U1.B15 | length 469.7
  Top Layer w10: L9.1@-694.88,-157.48 -649.61,-157.48 -620.08,-127.95 -442.91,-127.95 ; pad.0@-442.91,-157.48 -442.91,-127.95 ; U1.B15@-374.02,-137.8 -383.86,-127.95 -442.91,-127.95
  Bottom Layer w10: C15.1@-545.87,-157.48 pad.0@-442.91,-157.48
VTRX4: C18.1 L12.1 pad.0@-442.91,-314.96 U1.B19 | length 469.7
  Top Layer w10: L12.1@-694.88,-314.96 -649.61,-314.96 -620.08,-285.43 -442.91,-285.43 ; pad.0@-442.91,-314.96 -442.91,-285.43 ; U1.B19@-374.02,-295.28 -383.86,-285.43 -442.91,-285.43
  Bottom Layer w10: C18.1@-545.87,-314.96 pad.0@-442.91,-314.96
VTTX: C5.1 L2.2 L5.2 L8.2 L11.2 pad.0@-582.68,500 pad.0@-761.81,-78.74 pad.0@-761.81,-236.22 pad.0@-958.66,196.85 pad.0@-958.66,354.33 pad.0@-1121.1,413.39 U5.3 | length 1489.5
  MIdLayer5 w19.68: pad.0@-1121.1,413.39 -1017.72,413.39 pad.0@-958.66,354.33 ; pad.0@-958.66,196.85 -895.67,259.84 -895.67,291.34 pad.0@-958.66,354.33 ; pad.0@-761.81,-236.22 -698.82,-173.23 -698.82,-141.73 pad.0@-761.81,-78.74 -728.35,-45.28 -728.35,354.33 ; pad.0@-582.68,500 -728.35,354.33 ; pad.0@-958.66,354.33 -728.35,354.33
VTTX1: C8.1 L2.1 U1.B3 | length 557.6
  Top Layer w10: L2.1@-891.73,354.33 -639.76,354.33 -629.92,344.49 -551.18,344.49 ; C8.1@-545.87,314.96 -545.87,339.17 -551.18,344.49 ; U1.B3@-374.02,334.65 -383.86,344.49 -551.18,344.49
VTTX2: C11.1 L5.1 U1.B7 | length 557.6
  Top Layer w10: L5.1@-891.73,196.85 -639.76,196.85 -629.92,187.01 -551.18,187.01 ; C11.1@-545.87,157.48 -545.87,181.69 -551.18,187.01 ; U1.B7@-374.02,177.17 -383.86,187.01 -551.18,187.01
VTTX3: C14.1 L8.1 pad.0@-442.91,-78.74 U1.B13 | length 469.7
  Top Layer w10: L8.1@-694.88,-78.74 -649.61,-78.74 -620.08,-49.21 -442.91,-49.21 ; pad.0@-442.91,-78.74 -442.91,-49.21 ; U1.B13@-374.02,-59.06 -383.86,-49.21 -442.91,-49.21
  Bottom Layer w10: C14.1@-545.87,-78.74 pad.0@-442.91,-78.74
VTTX4: C17.1 L11.1 pad.0@-442.91,-236.22 U1.B17 | length 469.7
  Top Layer w10: L11.1@-694.88,-236.22 -649.61,-236.22 -620.08,-206.69 -442.91,-206.69 ; pad.0@-442.91,-236.22 -442.91,-206.69 ; U1.B17@-374.02,-216.54 -383.86,-206.69 -442.91,-206.69
  Bottom Layer w10: C17.1@-545.87,-236.22 pad.0@-442.91,-236.22
pads on no net: H1.1 H2.1 J1.0 J2.0 J3.0 J4.0 J4.25 J4.48 J5.0 J5.25 J5.48 J5.49 J5.50 J6.0 J7.0 J8.0 J8.3 J8.6 J8.7 J8.8 J10.0 U1.A2 U1.AA1 U1.AA3 U1.AA4 U1.AA5 U1.AA6 U1.AA7 U1.AA8 U1.AA9 U1.AA10 U1.AA13 U1.AA14 U1.AA15 U1.AA16 U1.AA17 U1.AA18 U1.AA19 U1.AA20 U1.AB3 U1.AB4 U1.AB5 U1.AB6 U1.AB7 U1.AB8 U1.AB9 U1.AB10 U1.AB13 U1.AB14 U1.AB15 U1.AB16 U1.AB17 U1.AB18 U1.AB19 U1.AB20 U1.B12 U1.C2 U1.C4 U1.C5 U1.C7 U1.C8 U1.C10 U1.C11 U1.C12 U1.C13 U1.C15 U1.C16 U1.C18 U1.C22 U1.D5 U1.D6 U1.D7 U1.D8 U1.D9 U1.D10 U1.D11 U1.D12 U1.D13 U1.D14 U1.D15 U1.D16 U1.D17 U1.D18 U1.E2 U1.E6 U1.E7 U1.E8 U1.E9 U1.E10 U1.E11 U1.E12 U1.E13 U1.E14 U1.E15 U1.E16 U1.E17 U1.E19 U1.F5 U1.F9 U1.F10 U1.F11 U1.F12 U1.F13 U1.F14 U1.F18 U1.F19 U1.G5 U1.G18 U1.H5 U1.H18 U1.J4 U1.J5 U1.J6 U1.J17 U1.J18 U1.K1 U1.K5 U1.K6 U1.K17 U1.K18 U1.K20 U1.K22 U1.L4 U1.L5 U1.L6 U1.L17 U1.L18 U1.M5 U1.M6 U1.M17 U1.M18 U1.N5 U1.N6 U1.N17 U1.N18 U1.N22 U1.P1 U1.P5 U1.P6 U1.P17 U1.P18 U1.R5 U1.Y19 U2.3 U2.4 U2.6 U7.2 U7.9 U7.12 U7.13 U7.14 U7.15 U7.16

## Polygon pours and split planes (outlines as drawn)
GND on MidLayer1 (hatched 90Degree grid 6 track 6, remove dead copper): -1475.28,728.35 -1475.28,-728.35 4066.06,-728.35 4066.06,728.35
+3.3V on MidLayer6 (hatched 90Degree grid 6 track 6, remove dead copper): -1476.38,728.35 -1476.38,-728.35 4064.96,-728.35 4064.96,728.35
+1.5V on MidLayer6 (hatched 90Degree grid 6 track 6, remove dead copper): -255.91,-255.91 334.65,-255.91 334.65,629.92 -255.91,629.92 -255.91,-255.91
+2.5V on MidLayer2 (hatched 90Degree grid 6 track 6, remove dead copper): -413.39,413.39 -413.39,-413.39 413.39,-413.39 413.39,413.39

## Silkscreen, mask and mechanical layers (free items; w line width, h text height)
Top Overlay:
  text "UMD HEP" at 3400,-200 h50
  text "2004" at 3400,-300 h50
Mechanical 1:
  lines w10: -1496.85,-750 -1496.85,750 4086.97,750 4086.97,-750 -1496.85,-750
  text "Hole Size                 Pads    Vias" at 800,2600 h60
  text "Layer Stack" at 3500,2600 h60
  text "----------------------------------------" at 800,2500 h60
  text "---------------------------------------------" at 3500,2500 h60
  text "9.842mil (0.25mm)            0     660" at 800,2400 h60
  text ".GTL                           Top Layer" at 3500,2400 h60
  text "19.685mil (0.5mm)            0      36" at 800,2300 h60
  text ".G1                            Inner Layer 1" at 3500,2300 h60
  text "30mil (0.762mm)             22       0" at 800,2200 h60
  text ".G2                            Inner Layer 2" at 3500,2200 h60
  text "53mil (1.3462mm)             8       0" at 800,2100 h60
  text ".G3                            Inner Layer 3" at 3500,2100 h60
  text "55.118mil (1.4mm)            6       0" at 800,2000 h60
  text ".G4                            Inner Layer 4" at 3500,2000 h60
  text "60mil (1.524mm)              7       0" at 800,1900 h60
  text ".G5                            Inner Layer 5" at 3500,1900 h60
  text "8 Layers - 0.062 FR4" at -1500,1800 h60
  text "100mil (2.54mm)              4       0" at 800,1800 h60
  text ".G6                            Inner Layer 6" at 3500,1800 h60
  text "All Vias CB100 Epoxy Filled" at -1500,1700 h60
  text "130mil (3.302mm)             2       0" at 800,1700 h60
  text ".GBL                           Bottom Layer" at 3500,1700 h60
  text "Green Solder Mask Top and Bottom" at -1500,1600 h60
  text "----------------------------------------" at 800,1600 h60
  text "White Silkscreen Top and Bottom" at -1500,1500 h60
  text "Total                       49     696" at 800,1500 h60
  text "Immersion Gold Finish" at -1500,1400 h60
  text "IPC 600 Class 2" at -1500,1300 h60

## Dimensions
-1496.85,750 to -1496.85,-750 on Mechanical 1
-1496.85,750 to 4086.97,750 on Mechanical 1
